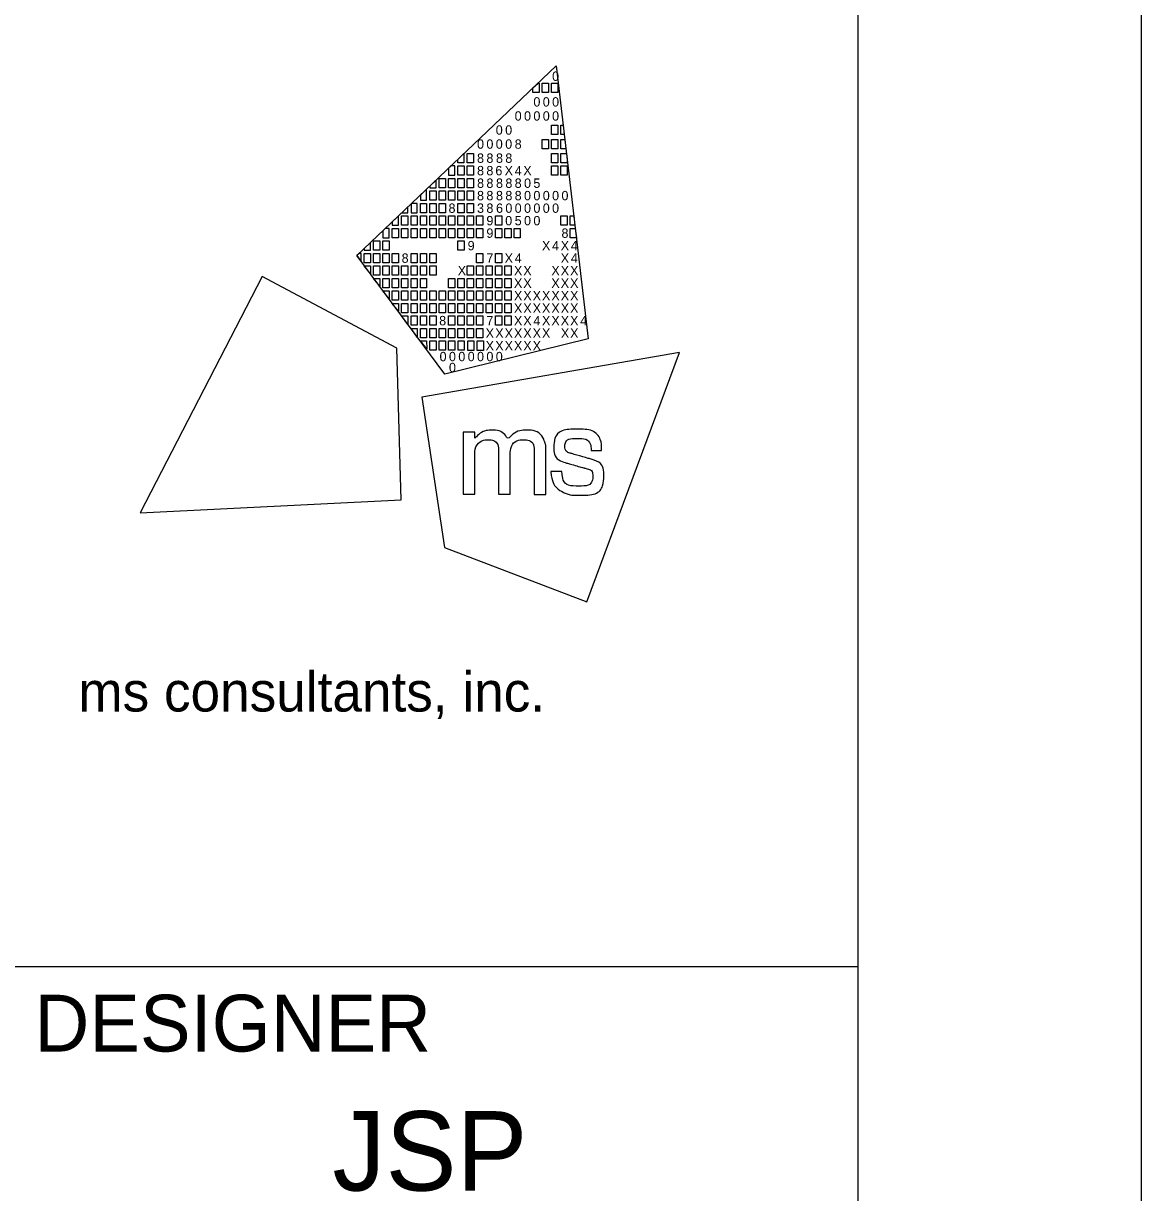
# Model space of a CAD drawing. Extents: x 0 to 34, y -14.6 to 28.2.
# Drawn here: x 32.03 to 34, y 2.102 to 4.161 of the extents above; entities that cross this region are included whole.
import ezdxf

# ---------------------------------------------------------------- set-up
doc = ezdxf.new("R2010")
doc.units = 0
for name, color, linetype in [('Default', 7, 'Continuous'), ('SH_Border', 7, 'Continuous'), ('SH_Cut_Line', 7, 'Continuous'), ('SH_Data', 7, 'Continuous')]:
    doc.layers.add(name, color=color, linetype=linetype)

msp = doc.modelspace()

# ---------------------------------------------------------------- linework, layer by layer
at = {"layer": 'Default'}
for p, q in [((32.6176, 3.7519), (32.9688, 4.0861)), ((32.9688, 4.0861), (32.9688, 4.0861)), ((32.9688, 4.0861), (33.0253, 3.6052)), ((32.773, 3.543), (32.6176, 3.7519)), ((33.0253, 3.6052), (32.773, 3.543))]:
    msp.add_line(p, q, dxfattribs=at)
for points in [[(32.9279, 4.0472), (32.9369, 4.0558), (32.939, 4.0558), (32.939, 4.0393), (32.9279, 4.0393)], [(32.9444, 4.0558), (32.9554, 4.0558), (32.9554, 4.0393), (32.9444, 4.0393)], [(32.9609, 4.0558), (32.9719, 4.0558), (32.9719, 4.0393), (32.9609, 4.0393)], [(32.9606, 3.9815), (32.9716, 3.9815), (32.9716, 3.965), (32.9606, 3.965)], [(32.9771, 3.9815), (32.9811, 3.9815), (32.983, 3.965), (32.9771, 3.965)], [(32.9442, 3.9567), (32.9552, 3.9567), (32.9552, 3.9402), (32.9442, 3.9402)], [(32.9606, 3.9567), (32.9716, 3.9567), (32.9716, 3.9402), (32.9606, 3.9402)], [(32.9771, 3.9567), (32.984, 3.9567), (32.9859, 3.9402), (32.9771, 3.9402)], [(32.7954, 3.9211), (32.8064, 3.9316), (32.8064, 3.9154), (32.7954, 3.9154)], [(32.8123, 3.9319), (32.8233, 3.9319), (32.8233, 3.9154), (32.8123, 3.9154)], [(32.9606, 3.9319), (32.9716, 3.9319), (32.9716, 3.9154), (32.9606, 3.9154)], [(32.9771, 3.9319), (32.9869, 3.9319), (32.9881, 3.9218), (32.9881, 3.9154), (32.9771, 3.9154)], [(32.7958, 3.9099), (32.8068, 3.9099), (32.8068, 3.8934), (32.7958, 3.8934)], [(32.8123, 3.9099), (32.8233, 3.9099), (32.8233, 3.8934), (32.8123, 3.8934)], [(32.9606, 3.9099), (32.9716, 3.9099), (32.9716, 3.8934), (32.9606, 3.8934)], [(32.9771, 3.9099), (32.9881, 3.9099), (32.9881, 3.8934), (32.9771, 3.8934)], [(32.7628, 3.8879), (32.7738, 3.8879), (32.7738, 3.8714), (32.7628, 3.8714)], [(32.7793, 3.8879), (32.7903, 3.8879), (32.7903, 3.8714), (32.7793, 3.8714)], [(32.7958, 3.8879), (32.8068, 3.8879), (32.8068, 3.8714), (32.7958, 3.8714)], [(32.8123, 3.8879), (32.8233, 3.8879), (32.8233, 3.8714), (32.8123, 3.8714)], [(32.7463, 3.8659), (32.7573, 3.8659), (32.7573, 3.8494), (32.7463, 3.8494)], [(32.7628, 3.8659), (32.7738, 3.8659), (32.7738, 3.8494), (32.7628, 3.8494)], [(32.7793, 3.8659), (32.7903, 3.8659), (32.7903, 3.8494), (32.7793, 3.8494)], [(32.7958, 3.8659), (32.8068, 3.8659), (32.8068, 3.8494), (32.7958, 3.8494)], [(32.8123, 3.8659), (32.8233, 3.8659), (32.8233, 3.8494), (32.8123, 3.8494)], [(32.7297, 3.8439), (32.7407, 3.8439), (32.7407, 3.8273), (32.7297, 3.8273)], [(32.7463, 3.8439), (32.7573, 3.8439), (32.7573, 3.8273), (32.7463, 3.8273)], [(32.7628, 3.8439), (32.7738, 3.8439), (32.7738, 3.8273), (32.7628, 3.8273)], [(32.7958, 3.8439), (32.8068, 3.8439), (32.8068, 3.8273), (32.7958, 3.8273)], [(32.8123, 3.8439), (32.8233, 3.8439), (32.8233, 3.8273), (32.8123, 3.8273)], [(32.6967, 3.8218), (32.7077, 3.8218), (32.7077, 3.8053), (32.6967, 3.8053)], [(32.7132, 3.8218), (32.7242, 3.8218), (32.7242, 3.8053), (32.7132, 3.8053)], [(32.7297, 3.8218), (32.7407, 3.8218), (32.7407, 3.8053), (32.7297, 3.8053)], [(32.7463, 3.8218), (32.7573, 3.8218), (32.7573, 3.8053), (32.7463, 3.8053)], [(32.7628, 3.8218), (32.7738, 3.8218), (32.7738, 3.8053), (32.7628, 3.8053)], [(32.7793, 3.8218), (32.7903, 3.8218), (32.7903, 3.8053), (32.7793, 3.8053)], [(32.7958, 3.8218), (32.8068, 3.8218), (32.8068, 3.8053), (32.7958, 3.8053)], [(32.8123, 3.8218), (32.8233, 3.8218), (32.8233, 3.8053), (32.8123, 3.8053)], [(32.8288, 3.8218), (32.8398, 3.8218), (32.8398, 3.8053), (32.8288, 3.8053)], [(32.8618, 3.8218), (32.8729, 3.8218), (32.8729, 3.8053), (32.8618, 3.8053)], [(32.9771, 3.8218), (32.9881, 3.8218), (32.9881, 3.8053), (32.9771, 3.8053)], [(32.9936, 3.8218), (32.9999, 3.8218), (33.0018, 3.8053), (32.9936, 3.8053)], [(32.6802, 3.7998), (32.6912, 3.7998), (32.6912, 3.7833), (32.6802, 3.7833)], [(32.6967, 3.7998), (32.7077, 3.7998), (32.7077, 3.7833), (32.6967, 3.7833)], [(32.7132, 3.7998), (32.7242, 3.7998), (32.7242, 3.7833), (32.7132, 3.7833)], [(32.7297, 3.7998), (32.7407, 3.7998), (32.7407, 3.7833), (32.7297, 3.7833)], [(32.7463, 3.7998), (32.7573, 3.7998), (32.7573, 3.7833), (32.7463, 3.7833)], [(32.7628, 3.7998), (32.7738, 3.7998), (32.7738, 3.7833), (32.7628, 3.7833)], [(32.7793, 3.7998), (32.7903, 3.7998), (32.7903, 3.7833), (32.7793, 3.7833)], [(32.7958, 3.7998), (32.8068, 3.7998), (32.8068, 3.7833), (32.7958, 3.7833)], [(32.8123, 3.7998), (32.8233, 3.7998), (32.8233, 3.7833), (32.8123, 3.7833)], [(32.8288, 3.7998), (32.8398, 3.7998), (32.8398, 3.7833), (32.8288, 3.7833)], [(32.8618, 3.7998), (32.8729, 3.7998), (32.8729, 3.7833), (32.8618, 3.7833)], [(32.8784, 3.7998), (32.8894, 3.7998), (32.8894, 3.7833), (32.8784, 3.7833)], [(32.8947, 3.7998), (32.9057, 3.7998), (32.9057, 3.7833), (32.8947, 3.7833)], [(32.9936, 3.7998), (33.0024, 3.7998), (33.0044, 3.7833), (32.9936, 3.7833)], [(32.6472, 3.7778), (32.6582, 3.7778), (32.6582, 3.7613), (32.6472, 3.7613)], [(32.6637, 3.7778), (32.6747, 3.7778), (32.6747, 3.7613), (32.6637, 3.7613)], [(32.7958, 3.7778), (32.8068, 3.7778), (32.8068, 3.7613), (32.7958, 3.7613)], [(32.6307, 3.7558), (32.6417, 3.7558), (32.6417, 3.7393), (32.6307, 3.7393)], [(32.6472, 3.7558), (32.6582, 3.7558), (32.6582, 3.7393), (32.6472, 3.7393)], [(32.6637, 3.7558), (32.6747, 3.7558), (32.6747, 3.7393), (32.6637, 3.7393)], [(32.6802, 3.7558), (32.6912, 3.7558), (32.6912, 3.7393), (32.6802, 3.7393)], [(32.7132, 3.7558), (32.7242, 3.7558), (32.7242, 3.7393), (32.7132, 3.7393)], [(32.7297, 3.7558), (32.7407, 3.7558), (32.7407, 3.7393), (32.7297, 3.7393)], [(32.7463, 3.7558), (32.7573, 3.7558), (32.7573, 3.7393), (32.7463, 3.7393)], [(32.8288, 3.7558), (32.8398, 3.7558), (32.8398, 3.7393), (32.8288, 3.7393)], [(32.8618, 3.7558), (32.8729, 3.7558), (32.8729, 3.7393), (32.8618, 3.7393)], [(32.6307, 3.7338), (32.6417, 3.7338), (32.6417, 3.72)], [(32.6472, 3.7338), (32.6582, 3.7338), (32.6582, 3.7173), (32.6472, 3.7173)], [(32.6637, 3.7338), (32.6747, 3.7338), (32.6747, 3.7173), (32.6637, 3.7173)], [(32.6802, 3.7338), (32.6912, 3.7338), (32.6912, 3.7173), (32.6802, 3.7173)], [(32.6967, 3.7338), (32.7077, 3.7338), (32.7077, 3.7173), (32.6967, 3.7173)], [(32.7132, 3.7338), (32.7242, 3.7338), (32.7242, 3.7173), (32.7132, 3.7173)], [(32.7297, 3.7338), (32.7407, 3.7338), (32.7407, 3.7173), (32.7297, 3.7173)], [(32.7463, 3.7338), (32.7573, 3.7338), (32.7573, 3.7173), (32.7463, 3.7173)], [(32.8123, 3.7338), (32.8233, 3.7338), (32.8233, 3.7173), (32.8123, 3.7173)], [(32.8288, 3.7338), (32.8398, 3.7338), (32.8398, 3.7173), (32.8288, 3.7173)], [(32.8453, 3.7338), (32.8563, 3.7338), (32.8563, 3.7173), (32.8453, 3.7173)], [(32.8618, 3.7338), (32.8729, 3.7338), (32.8729, 3.7173), (32.8618, 3.7173)], [(32.8784, 3.7338), (32.8894, 3.7338), (32.8894, 3.7173), (32.8784, 3.7173)], [(32.6472, 3.7117), (32.6582, 3.7117), (32.6582, 3.698)], [(32.6637, 3.7117), (32.6747, 3.7117), (32.6747, 3.6952), (32.6637, 3.6952)], [(32.6802, 3.7117), (32.6912, 3.7117), (32.6912, 3.6952), (32.6802, 3.6952)], [(32.6967, 3.7117), (32.7077, 3.7117), (32.7077, 3.6952), (32.6967, 3.6952)], [(32.7132, 3.7117), (32.7242, 3.7117), (32.7242, 3.6952), (32.7132, 3.6952)], [(32.7297, 3.7117), (32.7407, 3.7117), (32.7407, 3.6952), (32.7297, 3.6952)], [(32.7793, 3.7117), (32.7903, 3.7117), (32.7903, 3.6952), (32.7793, 3.6952)], [(32.7958, 3.7117), (32.8068, 3.7117), (32.8068, 3.6952), (32.7958, 3.6952)], [(32.8123, 3.7117), (32.8233, 3.7117), (32.8233, 3.6952), (32.8123, 3.6952)], [(32.8288, 3.7117), (32.8398, 3.7117), (32.8398, 3.6952), (32.8288, 3.6952)], [(32.8453, 3.7117), (32.8563, 3.7117), (32.8563, 3.6952), (32.8453, 3.6952)], [(32.8618, 3.7117), (32.8729, 3.7117), (32.8729, 3.6952), (32.8618, 3.6952)], [(32.8784, 3.7117), (32.8894, 3.7117), (32.8894, 3.6952), (32.8784, 3.6952)], [(32.6637, 3.6897), (32.6747, 3.6897), (32.6747, 3.676)], [(32.6747, 3.6897), (32.6747, 3.6897), (32.6747, 3.6897)], [(32.6802, 3.6897), (32.6912, 3.6897), (32.6912, 3.6732), (32.6802, 3.6732)], [(32.6967, 3.6897), (32.7077, 3.6897), (32.7077, 3.6732), (32.6967, 3.6732)], [(32.7132, 3.6897), (32.7242, 3.6897), (32.7242, 3.6732), (32.7132, 3.6732)], [(32.7297, 3.6897), (32.7407, 3.6897), (32.7407, 3.6732), (32.7297, 3.6732)], [(32.7463, 3.6897), (32.7573, 3.6897), (32.7573, 3.6732), (32.7463, 3.6732)], [(32.7628, 3.6897), (32.7738, 3.6897), (32.7738, 3.6732), (32.7628, 3.6732)], [(32.7793, 3.6897), (32.7903, 3.6897), (32.7903, 3.6732), (32.7793, 3.6732)], [(32.7958, 3.6897), (32.8068, 3.6897), (32.8068, 3.6732), (32.7958, 3.6732)], [(32.8123, 3.6897), (32.8233, 3.6897), (32.8233, 3.6732), (32.8123, 3.6732)], [(32.8288, 3.6897), (32.8398, 3.6897), (32.8398, 3.6732), (32.8288, 3.6732)], [(32.8453, 3.6897), (32.8563, 3.6897), (32.8563, 3.6732), (32.8453, 3.6732)], [(32.8618, 3.6897), (32.8729, 3.6897), (32.8729, 3.6732), (32.8618, 3.6732)], [(32.8784, 3.6897), (32.8894, 3.6897), (32.8894, 3.6732), (32.8784, 3.6732)], [(32.6802, 3.6677), (32.6912, 3.6677), (32.6912, 3.654)], [(32.6967, 3.6677), (32.7077, 3.6677), (32.7077, 3.6512), (32.6967, 3.6512)], [(32.7132, 3.6677), (32.7242, 3.6677), (32.7242, 3.6512), (32.7132, 3.6512)], [(32.7297, 3.6677), (32.7407, 3.6677), (32.7407, 3.6512), (32.7297, 3.6512)], [(32.7463, 3.6677), (32.7573, 3.6677), (32.7573, 3.6512), (32.7463, 3.6512)], [(32.7628, 3.6677), (32.7738, 3.6677), (32.7738, 3.6512), (32.7628, 3.6512)], [(32.7793, 3.6677), (32.7903, 3.6677), (32.7903, 3.6512), (32.7793, 3.6512)], [(32.7958, 3.6677), (32.8068, 3.6677), (32.8068, 3.6512), (32.7958, 3.6512)], [(32.8123, 3.6677), (32.8233, 3.6677), (32.8233, 3.6512), (32.8123, 3.6512)], [(32.8288, 3.6677), (32.8398, 3.6677), (32.8398, 3.6512), (32.8288, 3.6512)], [(32.8453, 3.6677), (32.8563, 3.6677), (32.8563, 3.6512), (32.8453, 3.6512)], [(32.8618, 3.6677), (32.8729, 3.6677), (32.8729, 3.6512), (32.8618, 3.6512)], [(32.8784, 3.6677), (32.8894, 3.6677), (32.8894, 3.6512), (32.8784, 3.6512)], [(32.7078, 3.6305), (32.6966, 3.6457), (32.7078, 3.6457)], [(32.7132, 3.6457), (32.7242, 3.6457), (32.7242, 3.6292), (32.7132, 3.6292)], [(32.7297, 3.6457), (32.7407, 3.6457), (32.7407, 3.6292), (32.7297, 3.6292)], [(32.7463, 3.6457), (32.7573, 3.6457), (32.7573, 3.6292), (32.7463, 3.6292)], [(32.7793, 3.6457), (32.7903, 3.6457), (32.7903, 3.6292), (32.7793, 3.6292)], [(32.7958, 3.6457), (32.8068, 3.6457), (32.8068, 3.6292), (32.7958, 3.6292)], [(32.8123, 3.6457), (32.8233, 3.6457), (32.8233, 3.6292), (32.8123, 3.6292)], [(32.8288, 3.6457), (32.8398, 3.6457), (32.8398, 3.6292), (32.8288, 3.6292)], [(32.8618, 3.6457), (32.8729, 3.6457), (32.8729, 3.6292), (32.8618, 3.6292)], [(32.8784, 3.6457), (32.8894, 3.6457), (32.8894, 3.6292), (32.8784, 3.6292)], [(32.724, 3.6082), (32.7132, 3.6237), (32.7242, 3.6237)], [(32.7297, 3.6237), (32.7407, 3.6237), (32.7407, 3.6072), (32.7297, 3.6072)], [(32.7463, 3.6237), (32.7573, 3.6237), (32.7573, 3.6072), (32.7463, 3.6072)], [(32.7628, 3.6237), (32.7738, 3.6237), (32.7738, 3.6072), (32.7628, 3.6072)], [(32.7793, 3.6237), (32.7903, 3.6237), (32.7903, 3.6072), (32.7793, 3.6072)], [(32.7958, 3.6237), (32.8068, 3.6237), (32.8068, 3.6072), (32.7958, 3.6072)], [(32.8123, 3.6237), (32.8233, 3.6237), (32.8233, 3.6072), (32.8123, 3.6072)], [(32.8288, 3.6237), (32.8398, 3.6237), (32.8398, 3.6072), (32.8288, 3.6072)], [(32.7302, 3.6017), (32.7407, 3.6017), (32.7408, 3.5875)], [(32.7463, 3.6017), (32.7573, 3.6017), (32.7573, 3.5852), (32.7463, 3.5852)], [(32.763, 3.6017), (32.774, 3.6017), (32.774, 3.5852), (32.763, 3.5852)], [(32.7794, 3.6017), (32.7904, 3.6017), (32.7904, 3.5852), (32.7794, 3.5852)], [(32.7961, 3.6017), (32.8071, 3.6017), (32.8071, 3.5852), (32.7961, 3.5852)], [(32.813, 3.6017), (32.824, 3.6017), (32.824, 3.5851), (32.813, 3.5851)], [(32.8296, 3.6017), (32.8407, 3.6017), (32.8407, 3.5851), (32.8296, 3.5851)]]:
    msp.add_lwpolyline(points, close=True, dxfattribs=at)
for points in [[(32.7903, 3.9099), (32.7836, 3.9099), (32.7793, 3.9058), (32.7793, 3.8934), (32.7903, 3.8934), (32.7903, 3.9099)], [(32.7573, 3.8849), (32.7463, 3.8744), (32.7463, 3.8714), (32.7573, 3.8714), (32.7573, 3.8849)], [(32.7407, 3.8691), (32.7297, 3.8587), (32.7297, 3.8494), (32.7407, 3.8494), (32.7407, 3.8691)], [(32.7077, 3.8377), (32.6968, 3.8273), (32.7077, 3.8273), (32.7077, 3.8377)], [(32.7242, 3.8439), (32.7142, 3.8439), (32.7132, 3.843), (32.7132, 3.8273), (32.7242, 3.8273), (32.7242, 3.8439)], [(32.6912, 3.822), (32.6802, 3.8115), (32.6802, 3.8053), (32.6912, 3.8053), (32.6912, 3.822)], [(32.6747, 3.7998), (32.6679, 3.7998), (32.6637, 3.7958), (32.6637, 3.7833), (32.6747, 3.7833), (32.6747, 3.7998)], [(32.6417, 3.7749), (32.6307, 3.7644), (32.6307, 3.7613), (32.6417, 3.7613), (32.6417, 3.7749)], [(32.6252, 3.7558), (32.6216, 3.7558), (32.6176, 3.7519), (32.6252, 3.7417), (32.6252, 3.7558)], [(32.4512, 3.7149), (32.2359, 3.2988), (32.6957, 3.3215), (32.6884, 3.5892), (32.4512, 3.7149)], [(33.0229, 3.1422), (33.1859, 3.5814), (32.7324, 3.5029), (32.7722, 3.2381), (33.0229, 3.1422)]]:
    msp.add_lwpolyline(points, dxfattribs=at)
for points in [[(32.8048, 3.3315), (32.8048, 3.3315), (32.8048, 3.4409), (32.8048, 3.4409), (32.8048, 3.4409), (32.8255, 3.4409), (32.8255, 3.4409), (32.8255, 3.4409), (32.8255, 3.4297), (32.8255, 3.4297), (32.8346, 3.4399), (32.8457, 3.4445), (32.8555, 3.4445), (32.8689, 3.4445), (32.8792, 3.4372), (32.8837, 3.4266), (32.8915, 3.4381), (32.905, 3.4446), (32.9166, 3.4446), (32.9325, 3.4446), (32.9451, 3.435), (32.9494, 3.4213), (32.9494, 3.4212), (32.9494, 3.4212), (32.9495, 3.4212), (32.9501, 3.419), (32.9507, 3.4172), (32.9507, 3.4071), (32.9507, 3.4071), (32.9507, 3.3314), (32.9507, 3.3314), (32.9507, 3.3314), (32.9303, 3.3314), (32.9303, 3.3314), (32.9303, 3.3314), (32.9303, 3.4048), (32.9303, 3.4048), (32.9303, 3.4201), (32.9219, 3.4274), (32.9111, 3.4274), (32.8995, 3.4274), (32.888, 3.4171), (32.888, 3.4001), (32.888, 3.4001), (32.888, 3.3315), (32.888, 3.3315), (32.888, 3.3315), (32.8674, 3.3315), (32.8674, 3.3315), (32.8674, 3.3315), (32.8674, 3.4059), (32.8674, 3.4059), (32.8674, 3.4203), (32.8588, 3.4274), (32.8497, 3.4274), (32.8384, 3.4274), (32.8254, 3.417), (32.8254, 3.3962), (32.8254, 3.3962), (32.8254, 3.3315), (32.8254, 3.3315), (32.8254, 3.3315), (32.8048, 3.3315), (32.8048, 3.3315)], [(32.9596, 3.3709), (32.9596, 3.3709), (32.9595, 3.3717), (32.9595, 3.3717), (32.9595, 3.3717), (32.9603, 3.3717), (32.9603, 3.3717), (32.9603, 3.3717), (32.9783, 3.3717), (32.9783, 3.3717), (32.9783, 3.3717), (32.9789, 3.3717), (32.9789, 3.3717), (32.9789, 3.3717), (32.979, 3.371), (32.979, 3.371), (32.9803, 3.3554), (32.9887, 3.346), (33.009, 3.346), (33.0273, 3.346), (33.0333, 3.3554), (33.0333, 3.3631), (33.0333, 3.3732), (33.0256, 3.3758), (33.0175, 3.378), (33.0175, 3.378), (32.987, 3.3867), (32.987, 3.3867), (32.9721, 3.3909), (32.9648, 3.4019), (32.9648, 3.4142), (32.9648, 3.4303), (32.9768, 3.4462), (33.0052, 3.4462), (33.0348, 3.4462), (33.0489, 3.4285), (33.0489, 3.4095), (33.0489, 3.4095), (33.0489, 3.4087), (33.0489, 3.4087), (33.0489, 3.4087), (33.0482, 3.4087), (33.0482, 3.4087), (33.0482, 3.4087), (33.0312, 3.4087), (33.0312, 3.4087), (33.0312, 3.4087), (33.0305, 3.4087), (33.0305, 3.4087), (33.0305, 3.4087), (33.0305, 3.4094), (33.0305, 3.4094), (33.0302, 3.4208), (33.0227, 3.43), (33.0056, 3.43), (32.9891, 3.43), (32.9843, 3.4218), (32.9843, 3.4157), (32.9843, 3.4108), (32.9869, 3.4059), (32.9959, 3.4033), (32.9959, 3.4033), (33.0255, 3.3948), (33.0255, 3.3948), (33.0462, 3.3889), (33.0527, 3.3777), (33.0527, 3.3639), (33.0527, 3.3462), (33.041, 3.3298), (33.0087, 3.3298), (32.9952, 3.3298), (32.9877, 3.3321), (32.9823, 3.3348), (32.9691, 3.3414), (32.961, 3.3536), (32.9596, 3.3709)]]:
    msp.add_open_spline(points, degree=3, dxfattribs=at)
at = {"layer": 'SH_Border'}
msp.add_line((32, 2.5), (33.5, 2.5), dxfattribs=at)
msp.add_lwpolyline([(1.5, 21.5), (33.5, 21.5), (33.5, 0.5), (1.5, 0.5)], close=True, dxfattribs=at)
at = {"layer": 'SH_Cut_Line'}
msp.add_lwpolyline([(0, 0), (34, 0), (34, 22), (0, 22)], close=True, dxfattribs=at)
at = {"layer": 'SH_Data'}
msp.add_line((32.75, 3.5), (32.75, 3.5), dxfattribs=at)

# ---------------------------------------------------------------- texts
at = {"layer": 'Default'}
for s, p in [('0', (32.9617, 4.0597)), ('0', (32.9288, 4.0145)), ('0', (32.9453, 4.0145)), ('0', (32.9617, 4.0145)), ('0', (32.8958, 3.9897)), ('0', (32.9123, 3.9897)), ('0', (32.9288, 3.9897)), ('0', (32.9453, 3.9897)), ('0', (32.9617, 3.9897)), ('0', (32.8625, 3.965)), ('0', (32.8791, 3.965)), ('0', (32.8295, 3.9402)), ('0', (32.846, 3.9402)), ('0', (32.8625, 3.9402)), ('0', (32.8791, 3.9402)), ('8', (32.8958, 3.9402)), ('8', (32.8295, 3.9154)), ('8', (32.846, 3.9154)), ('8', (32.8629, 3.9154)), ('8', (32.8793, 3.9154)), ('8', (32.8295, 3.8934)), ('8', (32.846, 3.8934)), ('6', (32.8618, 3.8934)), ('X', (32.8781, 3.8934)), ('4', (32.8959, 3.8934)), ('X', (32.911, 3.8934)), ('8', (32.8295, 3.8713)), ('8', (32.846, 3.8713)), ('8', (32.8629, 3.8713)), ('8', (32.8794, 3.8713)), ('8', (32.8958, 3.8713)), ('0', (32.9123, 3.8713)), ('5', (32.9287, 3.8713)), ('8', (32.8295, 3.8494)), ('8', (32.846, 3.8494)), ('8', (32.8629, 3.8494)), ('8', (32.8794, 3.8494)), ('8', (32.8958, 3.8494)), ('0', (32.9123, 3.8494)), ('0', (32.9288, 3.8494)), ('0', (32.9453, 3.8494)), ('0', (32.9617, 3.8494)), ('0', (32.9782, 3.8494)), ('8', (32.7793, 3.8273)), ('3', (32.8295, 3.8273)), ('8', (32.846, 3.8273)), ('6', (32.8629, 3.8273)), ('0', (32.8794, 3.8273)), ('0', (32.8958, 3.8273)), ('0', (32.9123, 3.8273)), ('0', (32.9288, 3.8273)), ('0', (32.9453, 3.8273)), ('0', (32.9617, 3.8273)), ('9', (32.846, 3.8053)), ('0', (32.8791, 3.8053)), ('5', (32.8958, 3.8053)), ('0', (32.9123, 3.8053)), ('0', (32.9288, 3.8053)), ('9', (32.846, 3.7833)), ('8', (32.9782, 3.7833)), ('9', (32.813, 3.7613)), ('X', (32.9439, 3.7613)), ('4', (32.9617, 3.7613)), ('X', (32.9769, 3.7613)), ('4', (32.9947, 3.7613)), ('8', (32.6967, 3.7393)), ('7', (32.846, 3.7393)), ('X', (32.8781, 3.7393)), ('4', (32.8959, 3.7393)), ('X', (32.9769, 3.7393)), ('4', (32.9947, 3.7393)), ('X', (32.7955, 3.7173)), ('X', (32.8945, 3.7173)), ('X', (32.911, 3.7173)), ('X', (32.9604, 3.7173)), ('X', (32.9769, 3.7173)), ('X', (32.9934, 3.7173)), ('X', (32.8945, 3.6952)), ('X', (32.911, 3.6952)), ('X', (32.9604, 3.6952)), ('X', (32.9769, 3.6952)), ('X', (32.9934, 3.6952)), ('X', (32.8945, 3.6732)), ('X', (32.911, 3.6732)), ('X', (32.9275, 3.6732)), ('X', (32.9439, 3.6732)), ('X', (32.9604, 3.6732)), ('X', (32.9769, 3.6732)), ('X', (32.9934, 3.6732)), ('X', (32.8945, 3.6512)), ('X', (32.911, 3.6512)), ('X', (32.9275, 3.6512)), ('X', (32.9439, 3.6512)), ('X', (32.9604, 3.6512)), ('X', (32.9769, 3.6512)), ('X', (32.9934, 3.6512)), ('8', (32.7628, 3.6292)), ('7', (32.846, 3.6292)), ('X', (32.8945, 3.6292)), ('X', (32.911, 3.6292)), ('4', (32.9288, 3.6292)), ('X', (32.9439, 3.6292)), ('X', (32.9604, 3.6292)), ('X', (32.9769, 3.6292)), ('X', (32.9934, 3.6292)), ('4', (33.0112, 3.6292)), ('X', (32.8447, 3.6072)), ('X', (32.8616, 3.6072)), ('X', (32.8781, 3.6072)), ('X', (32.8945, 3.6072)), ('X', (32.911, 3.6072)), ('X', (32.9275, 3.6072)), ('X', (32.9439, 3.6072)), ('X', (32.9772, 3.6072)), ('X', (32.9934, 3.6072)), ('X', (32.8447, 3.5851)), ('X', (32.8616, 3.5851)), ('X', (32.8781, 3.5851)), ('X', (32.8945, 3.5851)), ('X', (32.911, 3.5851)), ('X', (32.9275, 3.5851)), ('0', (32.7635, 3.5659)), ('0', (32.78, 3.5659)), ('0', (32.78, 3.5467)), ('0', (32.7965, 3.5659)), ('0', (32.813, 3.5659)), ('0', (32.8295, 3.5659)), ('0', (32.846, 3.5659)), ('0', (32.8625, 3.5659))]:
    msp.add_text(s, height=0.0165, rotation=360, dxfattribs=at).set_placement(p)
at = {"layer": 'SH_Border'}
msp.add_text('ms consultants, inc.', height=0.07, rotation=360, dxfattribs=at).set_placement((32.1273, 2.9489))
at = {"layer": 'SH_Data'}
for s, height, p in [('DESIGNER', 0.1, (32.05, 2.35)), ('JSP', 0.14, (32.5748, 2.105))]:
    msp.add_text(s, height=height, dxfattribs=at).set_placement(p)

doc.saveas('drawing.dxf')
